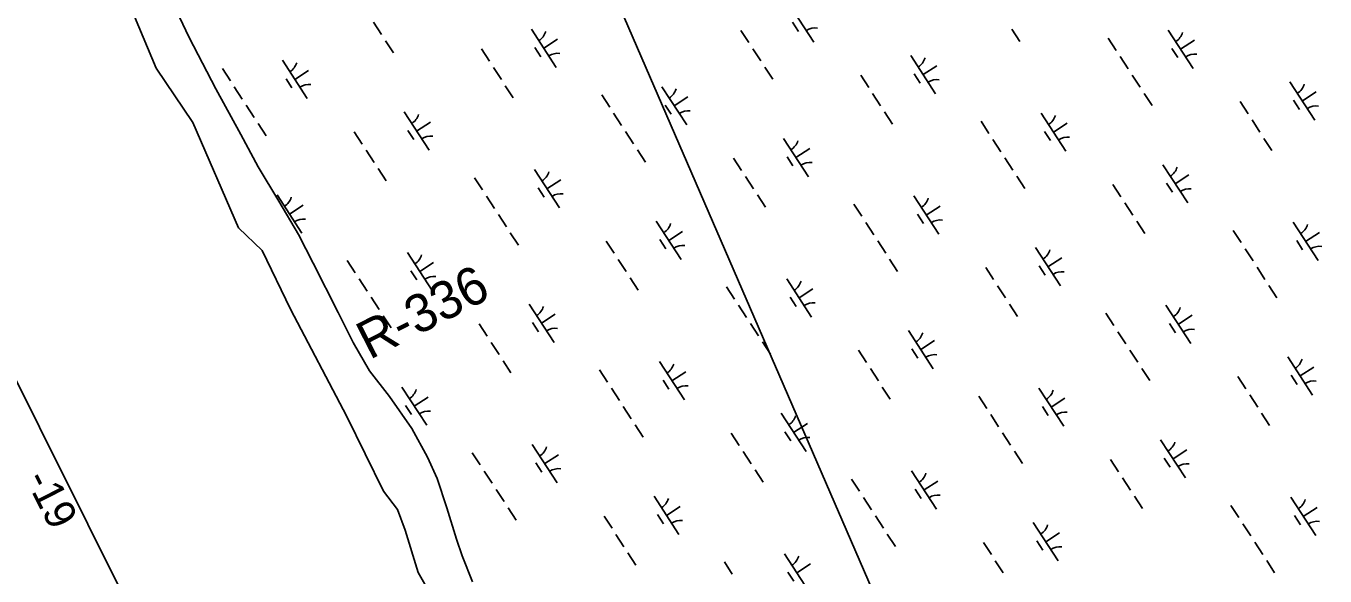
# Model space of a CAD drawing. Extents: x 3953924 to 3974542, y 193747 to 216192.
# Drawn here: x 3960676 to 3962100, y 209938 to 210540 of the extents above; entities that cross this region are included whole.
import ezdxf

# ---------------------------------------------------------------- set-up
doc = ezdxf.new("R2010")
doc.units = 0
for name, color, linetype in [('V-RIVR-EDGE', 7, 'Continuous'), ('V-RIVR-RANG', 7, 'Continuous'), ('V-RIVR-RANG-IDEN', 7, 'Continuous'), ('V-TOPO-DPTH', 7, 'Continuous'), ('V-UTIL-LINE', 7, 'Continuous'), ('V-WETL-SWMP', 7, 'Continuous')]:
    doc.layers.add(name, color=color, linetype=linetype)

msp = doc.modelspace()

# ---------------------------------------------------------------- linework, layer by layer
at = {"layer": 'V-RIVR-EDGE'}
msp.add_lwpolyline([(3960785.3, 210573.7), (3960818.5, 210494.2), (3960858.9, 210434.8), (3960908.8, 210319.6), (3960934.9, 210294.7), (3960965.8, 210230.6), (3961027.5, 210113.1), (3961067.9, 210031.1), (3961083.3, 210011), (3961091.6, 209988.4), (3961105.9, 209942.1), (3961141.5, 209879.2)], dxfattribs=at)
at = {"layer": 'V-TOPO-DPTH'}
msp.add_lwpolyline([(3961753.3, 207971.3), (3960371.5, 210740.9)], dxfattribs=at)
at = {"layer": 'V-UTIL-LINE'}
msp.add_lwpolyline([(3960964.1, 211397.1), (3962099.7, 208779.5)], dxfattribs=at)
at = {"layer": 'V-WETL-SWMP'}
for p, q in [((3960827, 210586.8), (3960854.7, 210528)), ((3961512.2, 210564.8), (3961539.5, 210522.9)), ((3961056.8, 210544.5), (3961065.6, 210531.1)), ((3961516.1, 210544.7), (3961522.6, 210534.6)), ((3960854.7, 210528), (3960883.9, 210471.6)), ((3961229.9, 210537), (3961257.2, 210495.1)), ((3961459.5, 210535.7), (3961468.2, 210522.3)), ((3961756.4, 210537), (3961765.2, 210523.6)), ((3961862.1, 210527), (3961870.8, 210513.6)), ((3961927.9, 210536), (3961955.2, 210494.1)), ((3961069.9, 210524.3), (3961078.7, 210510.9)), ((3961175.1, 210515.3), (3961183.9, 210501.9)), ((3961233.8, 210516.9), (3961240.3, 210506.8)), ((3961243.5, 210516.1), (3961258.6, 210525.9)), ((3961472.5, 210515.6), (3961481.3, 210502.2)), ((3961931.8, 210515.8), (3961938.3, 210505.8)), ((3961941.5, 210515), (3961956.6, 210524.8)), ((3960957.1, 210502.9), (3960984.3, 210461)), ((3961645.6, 210508.2), (3961672.9, 210466.3)), ((3961875.2, 210506.9), (3961883.9, 210493.5)), ((3960891.2, 210493.9), (3960900, 210480.5)), ((3960970.7, 210481.9), (3960985.8, 210491.7)), ((3961188.2, 210495.2), (3961197, 210481.8)), ((3961485.6, 210495.5), (3961494.4, 210482.1)), ((3961590.8, 210486.5), (3961599.6, 210473.1)), ((3961649.5, 210488), (3961656, 210478)), ((3961659.2, 210487.2), (3961674.3, 210497)), ((3961888.3, 210486.8), (3961897, 210473.4)), ((3960883.9, 210471.6), (3960911.5, 210421.8)), ((3960904.3, 210473.8), (3960913.1, 210460.4)), ((3960961, 210482.7), (3960967.5, 210472.7)), ((3961201.3, 210475.1), (3961210, 210461.7)), ((3961372.8, 210474), (3961400.1, 210432.1)), ((3962061.3, 210479.3), (3962088.6, 210437.4)), ((3961307, 210465.1), (3961315.7, 210451.7)), ((3961386.4, 210453.1), (3961401.5, 210462.9)), ((3961603.9, 210466.4), (3961612.7, 210453)), ((3961901.4, 210466.7), (3961910.1, 210453.3)), ((3962006.6, 210457.7), (3962015.3, 210444.3)), ((3962065.2, 210459.2), (3962071.8, 210449.2)), ((3962075, 210458.4), (3962090, 210468.2)), ((3960917.4, 210453.7), (3960926.2, 210440.3)), ((3961090.5, 210446.3), (3961117.8, 210404.4)), ((3961320, 210445), (3961328.8, 210431.6)), ((3961376.7, 210453.9), (3961383.2, 210443.9)), ((3961617, 210446.3), (3961625.8, 210432.9)), ((3961788.5, 210445.2), (3961815.8, 210403.3)), ((3960930.5, 210433.6), (3960939.2, 210420.2)), ((3961104.1, 210425.3), (3961119.2, 210435.1)), ((3961722.7, 210436.3), (3961731.4, 210422.9)), ((3961802.1, 210424.3), (3961817.2, 210434.1)), ((3962019.7, 210437.6), (3962028.4, 210424.1)), ((3960911.5, 210421.8), (3960930.5, 210386.1)), ((3961035.7, 210424.6), (3961044.5, 210411.2)), ((3961094.4, 210426.1), (3961100.9, 210416.1)), ((3961333.1, 210424.9), (3961341.9, 210411.5)), ((3961506.2, 210417.4), (3961533.5, 210375.5)), ((3961735.8, 210416.2), (3961744.5, 210402.8)), ((3961792.4, 210425.1), (3961798.9, 210415)), ((3962032.7, 210417.4), (3962041.5, 210404)), ((3961048.8, 210404.5), (3961057.5, 210391.1)), ((3961346.2, 210404.8), (3961355, 210391.4)), ((3961519.8, 210396.5), (3961534.9, 210406.3)), ((3960930.5, 210386.1), (3960953.1, 210348.6)), ((3961061.9, 210384.4), (3961070.6, 210370.9)), ((3961451.4, 210395.8), (3961460.2, 210382.3)), ((3961510.1, 210397.3), (3961516.6, 210387.2)), ((3961748.9, 210396.1), (3961757.6, 210382.6)), ((3961921.9, 210388.6), (3961949.2, 210346.7)), ((3961167.6, 210374.4), (3961176.3, 210361)), ((3961233.4, 210383.3), (3961260.6, 210341.4)), ((3961247, 210362.3), (3961262.1, 210372.2)), ((3961464.5, 210375.6), (3961473.3, 210362.2)), ((3961762, 210375.9), (3961770.7, 210362.5)), ((3961935.6, 210367.6), (3961950.6, 210377.5)), ((3960951.1, 210355.5), (3960978.4, 210313.6)), ((3961237.3, 210363.2), (3961243.8, 210353.1)), ((3961477.6, 210355.5), (3961486.4, 210342.1)), ((3961867.2, 210366.9), (3961875.9, 210353.5)), ((3961925.8, 210368.5), (3961932.4, 210358.4)), ((3960953.1, 210348.6), (3960974.6, 210312.1)), ((3960964.7, 210334.6), (3960979.8, 210344.4)), ((3961180.6, 210354.3), (3961189.4, 210340.8)), ((3961583.3, 210345.5), (3961592, 210332.1)), ((3961649.1, 210354.5), (3961676.4, 210312.6)), ((3961662.7, 210333.5), (3961677.8, 210343.3)), ((3961880.2, 210346.8), (3961889, 210333.4)), ((3961193.7, 210334.1), (3961202.5, 210320.7)), ((3961366.8, 210326.7), (3961394.1, 210284.8)), ((3961653, 210334.3), (3961659.5, 210324.3)), ((3961893.3, 210326.7), (3961902.1, 210313.3)), ((3961206.8, 210314), (3961215.6, 210300.6)), ((3961380.4, 210305.7), (3961395.5, 210315.6)), ((3961596.4, 210325.4), (3961605.1, 210312)), ((3961999, 210316.7), (3962007.7, 210303.3)), ((3962064.8, 210325.6), (3962092.1, 210283.7)), ((3962078.4, 210304.7), (3962093.5, 210314.5)), ((3960974.6, 210312.1), (3960990.9, 210280.7)), ((3961312, 210305), (3961320.8, 210291.6)), ((3961370.7, 210306.6), (3961377.2, 210296.5)), ((3961609.5, 210305.3), (3961618.2, 210291.9)), ((3962068.7, 210305.5), (3962075.2, 210295.4)), ((3961094, 210292.6), (3961121.2, 210250.7)), ((3961325.1, 210284.9), (3961333.9, 210271.5)), ((3961622.5, 210285.2), (3961631.3, 210271.8)), ((3961782.5, 210297.9), (3961809.8, 210255.9)), ((3961796.1, 210276.9), (3961811.2, 210286.7)), ((3962012.1, 210296.6), (3962020.8, 210283.2)), ((3960990.9, 210280.7), (3961018.1, 210226.8)), ((3961028.1, 210283.6), (3961036.9, 210270.2)), ((3961097.9, 210272.4), (3961104.4, 210262.4)), ((3961107.6, 210271.6), (3961122.7, 210281.4)), ((3961727.8, 210276.2), (3961736.5, 210262.8)), ((3961786.4, 210277.7), (3961793, 210267.7)), ((3962025.2, 210276.5), (3962033.9, 210263.1)), ((3961041.2, 210263.5), (3961050, 210250.1)), ((3961338.2, 210264.8), (3961347, 210251.4)), ((3961509.7, 210263.7), (3961537, 210221.8)), ((3961740.8, 210256.1), (3961749.6, 210242.7)), ((3962038.3, 210256.4), (3962047, 210243)), ((3961054.3, 210243.4), (3961063.1, 210230)), ((3961443.9, 210254.8), (3961452.6, 210241.4)), ((3961513.6, 210243.6), (3961520.1, 210233.5)), ((3961523.3, 210242.8), (3961538.4, 210252.6)), ((3961227.4, 210235.9), (3961254.7, 210194)), ((3961457, 210234.7), (3961465.7, 210221.3)), ((3961753.9, 210235.9), (3961762.7, 210222.5)), ((3961925.4, 210234.9), (3961952.7, 210193)), ((3961018.1, 210226.8), (3961034.7, 210193.8)), ((3961067.4, 210223.3), (3961076.2, 210209.9)), ((3961172.6, 210214.3), (3961181.4, 210200.9)), ((3961231.3, 210215.8), (3961237.8, 210205.7)), ((3961241, 210215), (3961256.1, 210224.8)), ((3961470, 210214.6), (3961478.8, 210201.2)), ((3961859.6, 210226), (3961868.3, 210212.6)), ((3961929.3, 210214.8), (3961935.8, 210204.7)), ((3961939, 210213.9), (3961954.1, 210223.8)), ((3961643.1, 210207.1), (3961670.4, 210165.2)), ((3961872.7, 210205.8), (3961881.4, 210192.4)), ((3961034.7, 210193.8), (3961052.4, 210163.1)), ((3961185.7, 210194.1), (3961194.5, 210180.7)), ((3961483.1, 210194.5), (3961491.9, 210181)), ((3961588.3, 210185.4), (3961597.1, 210172)), ((3961647, 210187), (3961653.5, 210176.9)), ((3961656.7, 210186.2), (3961671.8, 210196)), ((3961885.8, 210185.7), (3961894.5, 210172.3)), ((3961198.8, 210174), (3961207.5, 210160.6)), ((3961370.3, 210173), (3961397.6, 210131.1)), ((3962058.8, 210178.3), (3962086.1, 210136.4)), ((3961052.4, 210163.1), (3961074.5, 210134.7)), ((3961304.5, 210164), (3961313.2, 210150.6)), ((3961383.9, 210152), (3961399, 210161.8)), ((3961601.4, 210165.3), (3961610.2, 210151.9)), ((3961898.9, 210165.6), (3961907.6, 210152.2)), ((3962004.1, 210156.6), (3962012.8, 210143.2)), ((3962062.7, 210158.1), (3962069.3, 210148.1)), ((3962072.5, 210157.3), (3962087.5, 210167.1)), ((3961088, 210145.2), (3961115.3, 210103.3)), ((3961317.6, 210143.9), (3961326.3, 210130.5)), ((3961374.2, 210152.8), (3961380.7, 210142.8)), ((3961614.5, 210145.2), (3961623.3, 210131.8)), ((3961786, 210144.1), (3961813.3, 210102.2)), ((3961074.5, 210134.7), (3961098.7, 210099.8)), ((3961101.6, 210124.2), (3961116.7, 210134.1)), ((3961720.2, 210135.2), (3961728.9, 210121.8)), ((3961799.6, 210123.2), (3961814.7, 210133)), ((3962017.2, 210136.5), (3962025.9, 210123.1)), ((3961091.9, 210125.1), (3961098.4, 210115)), ((3961330.6, 210123.8), (3961339.4, 210110.4)), ((3961503.7, 210116.4), (3961531, 210074.5)), ((3961733.3, 210115.1), (3961742, 210101.7)), ((3961789.9, 210124), (3961796.4, 210114)), ((3962030.2, 210116.4), (3962039, 210103)), ((3961098.7, 210099.8), (3961116.1, 210068.5)), ((3961343.7, 210103.7), (3961352.5, 210090.3)), ((3961517.3, 210095.4), (3961532.4, 210105.2)), ((3961448.9, 210094.7), (3961457.7, 210081.3)), ((3961507.6, 210096.2), (3961514.1, 210086.2)), ((3961746.4, 210095), (3961755.1, 210081.6)), ((3961919.4, 210087.5), (3961946.7, 210045.6)), ((3961165.1, 210073.3), (3961173.8, 210059.9)), ((3961230.9, 210082.2), (3961258.2, 210040.3)), ((3961244.5, 210061.3), (3961259.6, 210071.1)), ((3961462, 210074.6), (3961470.8, 210061.2)), ((3961759.5, 210074.9), (3961768.2, 210061.5)), ((3961933.1, 210066.6), (3961948.1, 210076.4)), ((3961116.1, 210068.5), (3961126.5, 210045)), ((3961234.8, 210062.1), (3961241.3, 210052)), ((3961864.7, 210065.9), (3961873.4, 210052.4)), ((3961923.3, 210067.4), (3961929.9, 210057.3)), ((3961126.5, 210045), (3961137.2, 210012.9)), ((3961178.1, 210053.2), (3961186.9, 210039.8)), ((3961475.1, 210054.5), (3961483.9, 210041)), ((3961580.8, 210044.5), (3961589.5, 210031.1)), ((3961646.6, 210053.4), (3961673.9, 210011.5)), ((3961660.2, 210032.5), (3961675.3, 210042.3)), ((3961877.8, 210045.7), (3961886.5, 210032.3)), ((3961191.2, 210033.1), (3961200, 210019.7)), ((3961650.5, 210033.3), (3961657, 210023.2)), ((3961364.3, 210025.6), (3961391.6, 209983.7)), ((3961377.9, 210004.7), (3961393, 210014.5)), ((3961593.9, 210024.4), (3961602.6, 210010.9)), ((3961890.8, 210025.6), (3961899.6, 210012.2)), ((3961996.5, 210015.6), (3962005.2, 210002.2)), ((3962062.3, 210024.6), (3962089.6, 209982.7)), ((3962075.9, 210003.6), (3962091, 210013.4)), ((3961137.2, 210012.9), (3961148, 209978.8)), ((3961204.3, 210013), (3961213.1, 209999.6)), ((3961309.5, 210003.9), (3961318.3, 209990.5)), ((3961368.2, 210005.5), (3961374.7, 209995.4)), ((3961607, 210004.2), (3961615.7, 209990.8)), ((3962066.2, 210004.4), (3962072.8, 209994.4)), ((3961780, 209996.8), (3961807.3, 209954.9)), ((3961793.6, 209975.8), (3961808.7, 209985.7)), ((3962009.6, 209995.5), (3962018.3, 209982.1)), ((3961148, 209978.8), (3961154, 209960.5)), ((3961322.6, 209983.8), (3961331.4, 209970.4)), ((3961620, 209984.1), (3961628.8, 209970.7)), ((3961725.3, 209975.1), (3961734, 209961.7)), ((3961783.9, 209976.7), (3961790.5, 209966.6)), ((3962022.7, 209975.4), (3962031.4, 209962)), ((3961154, 209960.5), (3961165.5, 209932)), ((3961335.7, 209963.7), (3961344.5, 209950.3)), ((3961507.2, 209962.7), (3961534.5, 209920.8)), ((3961441.4, 209953.7), (3961450.1, 209940.3)), ((3961511.1, 209942.5), (3961517.6, 209932.5)), ((3961520.8, 209941.7), (3961535.9, 209951.5)), ((3961738.3, 209955), (3961747.1, 209941.6)), ((3962035.8, 209955.3), (3962044.5, 209941.9))]:
    msp.add_line(p, q, dxfattribs=at)
for centre, start, end in [((3961228.7, 210539.3), 302.2901, 343.8338), ((3961541.1, 210520.8), 82.2901, 123.8337), ((3961926.7, 210538.3), 302.2901, 343.8338), ((3960955.8, 210505.2), 302.2901, 343.8338), ((3961258.8, 210493), 82.2901, 123.8337), ((3961644.4, 210510.5), 302.2901, 343.8338), ((3961956.8, 210492), 82.2901, 123.8337), ((3960986, 210458.9), 82.2901, 123.8337), ((3961371.5, 210476.4), 302.2901, 343.8338), ((3961674.5, 210464.2), 82.2901, 123.8337), ((3962060.1, 210481.7), 302.2901, 343.8338), ((3961089.3, 210448.6), 302.2901, 343.8338), ((3961401.7, 210430.1), 82.2901, 123.8337), ((3961787.3, 210447.5), 302.2901, 343.8338), ((3962090.2, 210435.4), 82.2901, 123.8337), ((3961119.4, 210402.3), 82.2901, 123.8337), ((3961505, 210419.8), 302.2901, 343.8338), ((3961817.4, 210401.2), 82.2901, 123.8337), ((3961535.1, 210373.5), 82.2901, 123.8337), ((3961920.7, 210390.9), 302.2901, 343.8338), ((3961232.1, 210385.6), 302.2901, 343.8338), ((3961262.3, 210339.3), 82.2901, 123.8337), ((3961950.8, 210344.6), 82.2901, 123.8337), ((3960949.8, 210357.8), 302.2901, 343.8338), ((3961647.9, 210356.8), 302.2901, 343.8338), ((3960980, 210311.5), 82.2901, 123.8337), ((3961678, 210310.5), 82.2901, 123.8337), ((3961365.6, 210329), 302.2901, 343.8338), ((3962063.6, 210328), 302.2901, 343.8338), ((3961395.7, 210282.7), 82.2901, 123.8337), ((3962093.7, 210281.7), 82.2901, 123.8337), ((3961092.7, 210294.9), 302.2901, 343.8338), ((3961781.3, 210300.2), 302.2901, 343.8338), ((3961811.4, 210253.9), 82.2901, 123.8337), ((3961122.9, 210248.6), 82.2901, 123.8337), ((3961508.5, 210266.1), 302.2901, 343.8338), ((3961226.2, 210238.3), 302.2901, 343.8338), ((3961538.6, 210219.8), 82.2901, 123.8337), ((3961924.2, 210237.2), 302.2901, 343.8338), ((3961256.3, 210192), 82.2901, 123.8337), ((3961641.9, 210209.4), 302.2901, 343.8338), ((3961954.3, 210190.9), 82.2901, 123.8337), ((3961369, 210175.3), 302.2901, 343.8338), ((3961672, 210163.1), 82.2901, 123.8337), ((3962057.6, 210180.6), 302.2901, 343.8338), ((3961086.8, 210147.5), 302.2901, 343.8338), ((3961399.2, 210129), 82.2901, 123.8337), ((3961784.8, 210146.5), 302.2901, 343.8338), ((3962087.7, 210134.3), 82.2901, 123.8337), ((3961116.9, 210101.2), 82.2901, 123.8337), ((3961502.5, 210118.7), 302.2901, 343.8338), ((3961814.9, 210100.2), 82.2901, 123.8337), ((3961532.6, 210072.4), 82.2901, 123.8337), ((3961918.2, 210089.9), 302.2901, 343.8338), ((3961229.6, 210084.6), 302.2901, 343.8338), ((3961948.3, 210043.6), 82.2901, 123.8337), ((3961259.8, 210038.3), 82.2901, 123.8337), ((3961645.4, 210055.7), 302.2901, 343.8338), ((3961363.1, 210027.9), 302.2901, 343.8338), ((3961675.5, 210009.4), 82.2901, 123.8337), ((3962061.1, 210026.9), 302.2901, 343.8338), ((3961393.2, 209981.6), 82.2901, 123.8337), ((3961778.8, 209999.1), 302.2901, 343.8338), ((3962091.2, 209980.6), 82.2901, 123.8337), ((3961506, 209965), 302.2901, 343.8338), ((3961808.9, 209952.8), 82.2901, 123.8337)]:
    msp.add_arc(centre, 17.6, start, end, dxfattribs=at)

# ---------------------------------------------------------------- texts
at = {"layer": 'V-RIVR-RANG'}
msp.add_text('-19', height=33.5, rotation=296.9463, dxfattribs=at).set_placement((3960674.7, 210044.6))
at = {"layer": 'V-RIVR-RANG-IDEN'}
msp.add_text('R-336', height=41.5, rotation=27.1694, dxfattribs=at).set_placement((3961052.6, 210174.6))

doc.saveas('drawing.dxf')
